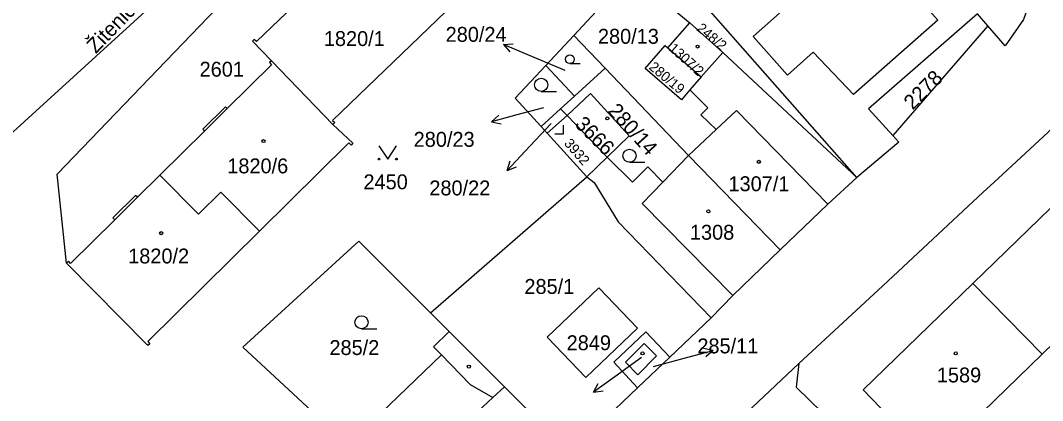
# Model space of a CAD drawing. Extents: x -679220 to -673243, y -1075091 to -1066557.
# Drawn here: x -676221 to -676104.3, y -1072066.3 to -1072022.8 of the extents above; entities that cross this region are included whole.
import ezdxf

# ---------------------------------------------------------------- set-up
doc = ezdxf.new("R2010")
doc.units = 0
for name, color, linetype in [('Hranice parcel', 7, 'Continuous'), ('Parcelní čísla', 7, 'Continuous'), ('Pop  PČ popisy', 7, 'Continuous'), ('Vnitřní kresba', 7, 'Continuous'), ('Značky budov', 7, 'Continuous'), ('Značky kultur', 7, 'Continuous')]:
    doc.layers.add(name, color=color, linetype=linetype)

msp = doc.modelspace()

# ---------------------------------------------------------------- linework, layer by layer
at = {"layer": 'Hranice parcel'}
for p, q in [((-676125.53, -1072040.78), (-676147.15, -1072016.17)), ((-676151.3, -1072017.54), (-676157.81, -1072024.54)), ((-676149.31, -1072019.2), (-676144.59, -1072023.12)), ((-676147.1, -1072025.95), (-676144.59, -1072023.12)), ((-676144.59, -1072023.12), (-676140.8, -1072026.5)), ((-676110.57, -1072023.44), (-676121.41, -1072035.99)), ((-676161.02, -1072027.99), (-676157.81, -1072024.54)), ((-676157.81, -1072024.54), (-676154.23, -1072028.3)), ((-676147.1, -1072025.95), (-676143.26, -1072029.26)), ((-676192.32, -1072027.45), (-676185.32, -1072034.72)), ((-676140.8, -1072026.5), (-676143.26, -1072029.26)), ((-676140.8, -1072026.5), (-676125.53, -1072040.78)), ((-676157.73, -1072031.5), (-676161.02, -1072027.99)), ((-676154.23, -1072028.3), (-676157.73, -1072031.5)), ((-676154.23, -1072028.3), (-676144.73, -1072038.28)), ((-676143.26, -1072029.26), (-676144.56, -1072030.77)), ((-676157.73, -1072031.5), (-676159.32, -1072032.95)), ((-676159.32, -1072032.95), (-676161.53, -1072034.97)), ((-676159.32, -1072032.95), (-676158.56, -1072033.71)), ((-676158.56, -1072033.71), (-676160.85, -1072035.71)), ((-676158.56, -1072033.71), (-676154.02, -1072038.44)), ((-676160.85, -1072035.71), (-676161.53, -1072034.97)), ((-676156.33, -1072040.69), (-676160.85, -1072035.71)), ((-676154.02, -1072038.44), (-676156.33, -1072040.69)), ((-676144.73, -1072038.28), (-676134.25, -1072049.05)), ((-676174.16, -1072056.23), (-676156.33, -1072040.69)), ((-676112.26, -1072052.87), (-676104.37, -1072060.94)), ((-676174.16, -1072056.23), (-676172.04, -1072058.35)), ((-676099.5, -1072056.21), (-676104.37, -1072060.94)), ((-676142.14, -1072056.79), (-676146.87, -1072061.29)), ((-676146.87, -1072061.29), (-676150.53, -1072064.78)), ((-676104.37, -1072060.94), (-676116.96, -1072073.18)), ((-676141.11, -1072070.44), (-676132.12, -1072062.03)), ((-676150.53, -1072064.78), (-676158.28, -1072072.17))]:
    msp.add_line(p, q, dxfattribs=at)
for points in [[(-676237.98, -1072058.25), (-676230.05, -1072050.34), (-676229.58, -1072042.66), (-676204.57, -1072019.81), (-676201.14, -1072018.7), (-676196.79, -1072017.28), (-676191.41, -1072012.1), (-676191.22, -1072005.71), (-676202.98, -1071993.28), (-676207.78, -1071991.04)], [(-676215.71, -1072050.56), (-676216.76, -1072040.4), (-676183.3, -1072005.53), (-676170.81, -1072002.39)], [(-676128.86, -1072008.55), (-676116.26, -1072022.8), (-676125.91, -1072031.3), (-676130.48, -1072026.48), (-676133.42, -1072029.08), (-676137.33, -1072024.66), (-676134.33, -1072022.01), (-676138.55, -1072017.24)], [(-676102.08, -1072008.38), (-676099.13, -1072013.08), (-676103.24, -1072014.32), (-676104.47, -1072016.46), (-676105.63, -1072020.23), (-676106.48, -1072022.75), (-676108.6, -1072025.74), (-676110.57, -1072023.44)], [(-676183.69, -1072015.28), (-676186.26, -1072017.75), (-676186.47, -1072017.53), (-676189.08, -1072020.05), (-676188.87, -1072020.27), (-676194.04, -1072025.25), (-676194.28, -1072025), (-676194.49, -1072025.2), (-676192.32, -1072027.45)], [(-676132.12, -1072062.03), (-676122.54, -1072053.13), (-676111.1, -1072042.44), (-676109.89, -1072041.36), (-676088.2, -1072021.23)], [(-676172.43, -1072021.81), (-676185.34, -1072034.26), (-676185.1, -1072034.51), (-676185.32, -1072034.72)], [(-676110.57, -1072023.44), (-676111.73, -1072022.1), (-676124.17, -1072032.92), (-676121.41, -1072035.99)], [(-676144.56, -1072030.77), (-676145.53, -1072031.9), (-676149.67, -1072028.33), (-676147.4, -1072025.69), (-676147.1, -1072025.95)], [(-676192.32, -1072027.45), (-676192.54, -1072027.65), (-676192.3, -1072027.9), (-676197.37, -1072032.91), (-676197.58, -1072032.7), (-676200.15, -1072035.25), (-676199.94, -1072035.46), (-676205.05, -1072040.51)], [(-676161.53, -1072034.97), (-676164.5, -1072031.73), (-676161.02, -1072027.99)], [(-676144.56, -1072030.77), (-676142.51, -1072032.81), (-676143.3, -1072033.6), (-676141.57, -1072035.31), (-676144.73, -1072038.28)], [(-676158.56, -1072033.71), (-676155.9, -1072031.17), (-676151.49, -1072036.01), (-676154.02, -1072038.44)], [(-676185.32, -1072034.72), (-676183.02, -1072036.86), (-676183.24, -1072037.07), (-676183.48, -1072036.82), (-676193.69, -1072046.91)], [(-676121.41, -1072035.99), (-676120.73, -1072036.75), (-676125.53, -1072040.78)], [(-676144.73, -1072038.28), (-676147.64, -1072041.3), (-676149.37, -1072039.56), (-676151.12, -1072041.29), (-676154.02, -1072038.44)], [(-676205.05, -1072040.51), (-676207.61, -1072043.04), (-676207.82, -1072042.82), (-676210.41, -1072045.39), (-676210.2, -1072045.6), (-676215.25, -1072050.6), (-676215.49, -1072050.35), (-676215.71, -1072050.56)], [(-676193.69, -1072046.91), (-676198.08, -1072042.45), (-676200.65, -1072044.97), (-676205.05, -1072040.51)], [(-676156.33, -1072040.69), (-676155.5, -1072041.36), (-676152.74, -1072045.84), (-676142.14, -1072056.79)], [(-676134.25, -1072049.05), (-676128.82, -1072043.82), (-676125.53, -1072040.78)], [(-676094.56, -1072045.83), (-676099.6, -1072040.58), (-676112.26, -1072052.87)], [(-676193.69, -1072046.91), (-676206.44, -1072059.51), (-676206.2, -1072059.76), (-676206.41, -1072059.97), (-676215.71, -1072050.56)], [(-676187.49, -1072068.2), (-676187.22, -1072067.91), (-676195.57, -1072060.17), (-676182.33, -1072048.06), (-676174.16, -1072056.23)], [(-676142.14, -1072056.79), (-676139.66, -1072054.27), (-676134.25, -1072049.05)], [(-676112.26, -1072052.87), (-676124.8, -1072065.03), (-676116.96, -1072073.18)], [(-676154.95, -1072053.37), (-676150.53, -1072057.97), (-676156.43, -1072063.61), (-676160.84, -1072059), (-676154.95, -1072053.37)], [(-676172.04, -1072058.35), (-676173.81, -1072060.11), (-676172.9, -1072061.03), (-676183.84, -1072071.54)], [(-676158.28, -1072072.17), (-676165.74, -1072064.68), (-676172.04, -1072058.35)], [(-676150.53, -1072064.78), (-676153.26, -1072061.87), (-676149.61, -1072058.39), (-676146.87, -1072061.29)], [(-676150.51, -1072063.32), (-676151.91, -1072061.88), (-676149.77, -1072059.72), (-676148.37, -1072061.16), (-676150.51, -1072063.32)], [(-676132.12, -1072062.03), (-676132.43, -1072064.73), (-676120.38, -1072076.5)]]:
    msp.add_lwpolyline(points, dxfattribs=at)
at = {"layer": 'Pop  PČ popisy'}
for p, q in [((-676165.83, -1072025.59), (-676164.72, -1072025.52)), ((-676163.07, -1072026.76), (-676165.83, -1072025.59)), ((-676165.83, -1072025.59), (-676165.11, -1072026.44)), ((-676158.8, -1072028.56), (-676163.07, -1072026.76)), ((-676161.27, -1072032.81), (-676164.3, -1072033.63)), ((-676164.3, -1072033.63), (-676167.2, -1072034.41)), ((-676167.2, -1072034.41), (-676166.36, -1072033.66)), ((-676167.2, -1072034.41), (-676166.1, -1072034.63)), ((-676160.41, -1072034.6), (-676163.36, -1072037.77)), ((-676163.36, -1072037.77), (-676165.41, -1072039.97)), ((-676165.41, -1072039.97), (-676165.09, -1072038.89)), ((-676165.41, -1072039.97), (-676164.36, -1072039.57)), ((-676150.08, -1072061.33), (-676153.14, -1072063.55)), ((-676148.73, -1072062.36), (-676144.8, -1072061.3)), ((-676144.8, -1072061.3), (-676141.9, -1072060.52)), ((-676141.9, -1072060.52), (-676143, -1072060.3)), ((-676141.9, -1072060.52), (-676142.74, -1072061.27)), ((-676153.14, -1072063.55), (-676155.57, -1072065.31)), ((-676155.57, -1072065.31), (-676155.05, -1072064.32)), ((-676155.57, -1072065.31), (-676154.46, -1072065.13))]:
    msp.add_line(p, q, dxfattribs=at)
at = {"layer": 'Vnitřní kresba'}
for p, q in [((-676199.94, -1072035.46), (-676197.37, -1072032.91)), ((-676141.57, -1072035.31), (-676139.25, -1072033.13)), ((-676139.25, -1072033.13), (-676128.82, -1072043.82)), ((-676147.64, -1072041.3), (-676150, -1072043.74)), ((-676210.2, -1072045.6), (-676207.61, -1072043.04)), ((-676150, -1072043.74), (-676139.66, -1072054.27)), ((-676172.9, -1072061.03), (-676169.63, -1072064.41)), ((-676169.63, -1072064.41), (-676167.07, -1072065.92)), ((-676167.07, -1072065.92), (-676165.74, -1072064.68)), ((-676169.33, -1072068.04), (-676167.07, -1072065.92))]:
    msp.add_line(p, q, dxfattribs=at)
at = {"layer": 'Značky budov'}
for centre in [(-676143.69, -1072025.82), (-676153.99, -1072034.03), (-676193.23, -1072036.62), (-676136.7, -1072038.99), (-676142.46, -1072044.64), (-676204.91, -1072047.13), (-676149.97, -1072060.86), (-676114.22, -1072060.86), (-676169.79, -1072062.38)]:
    msp.add_circle(centre, 0.175, dxfattribs=at)
at = {"layer": 'Značky kultur'}
for p, q in [((-676158.26, -1072027.77), (-676157.08, -1072027.77)), ((-676161.54, -1072030.94), (-676159.79, -1072030.94)), ((-676158.98, -1072035.79), (-676158.98, -1072034.79)), ((-676159.98, -1072035.79), (-676158.98, -1072035.79)), ((-676151.45, -1072039.04), (-676149.7, -1072039.04)), ((-676182.05, -1072058.06), (-676180.3, -1072058.06))]:
    msp.add_line(p, q, dxfattribs=at)
msp.add_lwpolyline([(-676180.05, -1072037.17), (-676179.05, -1072038.67), (-676178.05, -1072037.17)], dxfattribs=at)
for centre, radius in [((-676158.26, -1072027.27), 0.502), ((-676161.54, -1072030.19), 0.75), ((-676151.45, -1072038.29), 0.75), ((-676180.05, -1072038.67), 0.1), ((-676178.05, -1072038.67), 0.1), ((-676182.05, -1072057.31), 0.75)]:
    msp.add_circle(centre, radius, dxfattribs=at)

# ---------------------------------------------------------------- texts
at = {"layer": 'Parcelní čísla'}
for s, p in [('1820/1', (-676186.34, -1072025.76)), ('280/24', (-676172.44, -1072025.28)), ('280/13', (-676155.06, -1072025.5)), ('2601', (-676200.52, -1072029.26)), ('280/23', (-676176.09, -1072037.27)), ('1820/6', (-676197.36, -1072040.3)), ('2450', (-676181.82, -1072042.12)), ('280/22', (-676174.3, -1072042.82)), ('1307/1', (-676140.16, -1072042.34)), ('1308', (-676144.56, -1072047.88)), ('1820/2', (-676208.67, -1072050.59)), ('285/1', (-676163.45, -1072054.07)), ('2849', (-676158.63, -1072060.5)), ('285/11', (-676143.71, -1072060.86)), ('285/2', (-676185.7, -1072061.05)), ('1589', (-676116.38, -1072064.18))]:
    msp.add_text(s, height=1.7, dxfattribs=at).set_placement(p)
for s, height, rotation, p in [('248/2', 1.14, 320, (-676143.88, -1072023.9)), ('1307/2', 1.14, 318, (-676147.06, -1072026.16)), ('280/19', 1.14, 320, (-676149.33, -1072028.31)), ('2278', 1.7, 45, (-676119.14, -1072033.14)), ('280/14', 1.7, 312, (-676154.03, -1072033.24)), ('3666', 1.7, 315, (-676157.79, -1072034.81)), ('3932', 1.14, 311, (-676158.99, -1072036.93))]:
    msp.add_text(s, height=height, rotation=rotation, dxfattribs=at).set_placement(p)
at = {"layer": 'Pop  PČ popisy'}
msp.add_text('Žitenická', height=1.7, rotation=46, dxfattribs=at).set_placement((-676212.36, -1072026.7))

doc.saveas('drawing.dxf')
